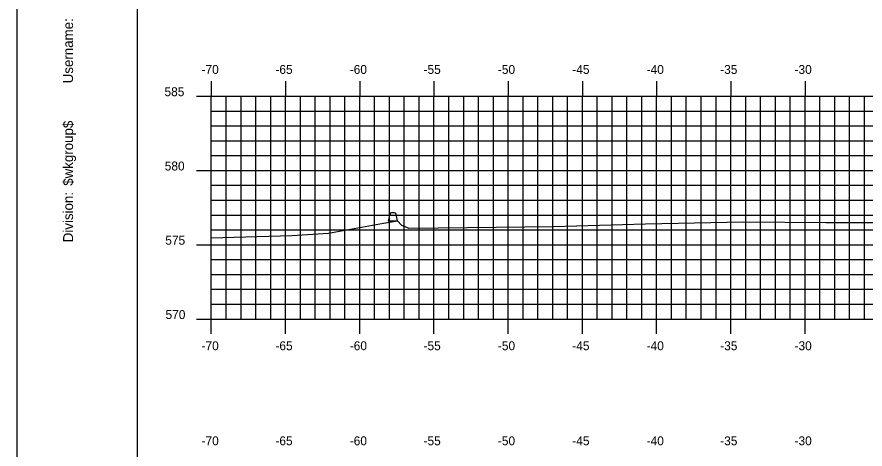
# Model space of a CAD drawing. Extents: x 1048343 to 1048513, y 781387 to 781497.
# Drawn here: x 1048343 to 1048400.2, y 781417.6 to 781446.7 of the extents above; entities that cross this region are included whole.
import ezdxf

# ---------------------------------------------------------------- set-up
doc = ezdxf.new("R2010")
doc.units = 0
for name, color, linetype in [('BORDER', 7, 'Continuous'), ('H_V ANNOTATION', 7, 'Continuous'), ('MAJOR', 7, 'Continuous'), ('MINOR', 7, 'Continuous'), ('PLOT BOUNDARY', 7, 'Continuous'), ('S_Curb_Type_3', 7, 'Continuous'), ('S_Roadway_Centerline', 7, 'Continuous')]:
    doc.layers.add(name, color=color, linetype=linetype)

msp = doc.modelspace()

# ---------------------------------------------------------------- linework, layer by layer
at = {"layer": 'BORDER'}
msp.add_lwpolyline([(1048351.12, 781390.375), (1048511.12, 781390.375), (1048511.12, 781495.375), (1048351.12, 781495.375)], close=True, dxfattribs=at)
at = {"layer": 'MAJOR'}
for p, q in [((1048356.119, 781442.377), (1048356.119, 781441.375)), ((1048361.119, 781442.377), (1048361.119, 781441.375)), ((1048366.119, 781442.377), (1048366.119, 781441.375)), ((1048371.119, 781442.377), (1048371.119, 781441.375)), ((1048376.119, 781442.377), (1048376.119, 781441.375)), ((1048381.119, 781442.377), (1048381.119, 781441.375)), ((1048386.119, 781442.377), (1048386.119, 781441.375)), ((1048391.119, 781442.377), (1048391.119, 781441.375)), ((1048396.119, 781442.377), (1048396.119, 781441.375)), ((1048355.117, 781441.375), (1048356.119, 781441.375)), ((1048356.119, 781441.375), (1048496.119, 781441.375)), ((1048356.119, 781426.375), (1048356.119, 781441.375)), ((1048356.119, 781426.375), (1048356.119, 781441.375)), ((1048356.119, 781441.375), (1048496.119, 781441.375)), ((1048361.119, 781426.375), (1048361.119, 781441.375)), ((1048366.119, 781426.375), (1048366.119, 781441.375)), ((1048371.119, 781426.375), (1048371.119, 781441.375)), ((1048376.119, 781426.375), (1048376.119, 781441.375)), ((1048381.119, 781426.375), (1048381.119, 781441.375)), ((1048386.119, 781426.375), (1048386.119, 781441.375)), ((1048391.119, 781426.375), (1048391.119, 781441.375)), ((1048396.119, 781426.375), (1048396.119, 781441.375)), ((1048355.117, 781436.375), (1048356.119, 781436.375)), ((1048356.119, 781436.375), (1048496.119, 781436.375)), ((1048355.117, 781431.375), (1048356.119, 781431.375)), ((1048356.119, 781431.375), (1048496.119, 781431.375)), ((1048355.117, 781426.375), (1048356.119, 781426.375)), ((1048356.119, 781426.375), (1048496.119, 781426.375)), ((1048356.119, 781426.375), (1048496.119, 781426.375)), ((1048356.119, 781425.373), (1048356.119, 781426.375)), ((1048361.119, 781425.373), (1048361.119, 781426.375)), ((1048366.119, 781425.373), (1048366.119, 781426.375)), ((1048371.119, 781425.373), (1048371.119, 781426.375)), ((1048376.119, 781425.373), (1048376.119, 781426.375)), ((1048381.119, 781425.373), (1048381.119, 781426.375)), ((1048386.119, 781425.373), (1048386.119, 781426.375)), ((1048391.119, 781425.373), (1048391.119, 781426.375)), ((1048396.119, 781425.373), (1048396.119, 781426.375))]:
    msp.add_line(p, q, dxfattribs=at)
at = {"layer": 'MINOR'}
for p, q in [((1048357.119, 781426.375), (1048357.119, 781441.375)), ((1048358.119, 781426.375), (1048358.119, 781441.375)), ((1048359.119, 781426.375), (1048359.119, 781441.375)), ((1048360.119, 781426.375), (1048360.119, 781441.375)), ((1048362.119, 781426.375), (1048362.119, 781441.375)), ((1048363.119, 781426.375), (1048363.119, 781441.375)), ((1048364.119, 781426.375), (1048364.119, 781441.375)), ((1048365.119, 781426.375), (1048365.119, 781441.375)), ((1048367.119, 781426.375), (1048367.119, 781441.375)), ((1048368.119, 781426.375), (1048368.119, 781441.375)), ((1048369.119, 781426.375), (1048369.119, 781441.375)), ((1048370.119, 781426.375), (1048370.119, 781441.375)), ((1048372.119, 781426.375), (1048372.119, 781441.375)), ((1048373.119, 781426.375), (1048373.119, 781441.375)), ((1048374.119, 781426.375), (1048374.119, 781441.375)), ((1048375.119, 781426.375), (1048375.119, 781441.375)), ((1048377.119, 781426.375), (1048377.119, 781441.375)), ((1048378.119, 781426.375), (1048378.119, 781441.375)), ((1048379.119, 781426.375), (1048379.119, 781441.375)), ((1048380.119, 781426.375), (1048380.119, 781441.375)), ((1048382.119, 781426.375), (1048382.119, 781441.375)), ((1048383.119, 781426.375), (1048383.119, 781441.375)), ((1048384.119, 781426.375), (1048384.119, 781441.375)), ((1048385.119, 781426.375), (1048385.119, 781441.375)), ((1048387.119, 781426.375), (1048387.119, 781441.375)), ((1048388.119, 781426.375), (1048388.119, 781441.375)), ((1048389.119, 781426.375), (1048389.119, 781441.375)), ((1048390.119, 781426.375), (1048390.119, 781441.375)), ((1048392.119, 781426.375), (1048392.119, 781441.375)), ((1048393.119, 781426.375), (1048393.119, 781441.375)), ((1048394.119, 781426.375), (1048394.119, 781441.375)), ((1048395.119, 781426.375), (1048395.119, 781441.375)), ((1048397.119, 781426.375), (1048397.119, 781441.375)), ((1048398.119, 781426.375), (1048398.119, 781441.375)), ((1048399.119, 781426.375), (1048399.119, 781441.375)), ((1048400.119, 781426.375), (1048400.119, 781441.375)), ((1048356.119, 781440.375), (1048496.119, 781440.375)), ((1048356.119, 781440.375), (1048357.121, 781440.375)), ((1048356.119, 781439.375), (1048496.119, 781439.375)), ((1048356.119, 781439.375), (1048357.121, 781439.375)), ((1048356.119, 781438.375), (1048496.119, 781438.375)), ((1048356.119, 781438.375), (1048357.121, 781438.375)), ((1048356.119, 781437.375), (1048496.119, 781437.375)), ((1048356.119, 781437.375), (1048357.121, 781437.375)), ((1048356.119, 781435.375), (1048496.119, 781435.375)), ((1048356.119, 781435.375), (1048357.121, 781435.375)), ((1048356.119, 781434.375), (1048496.119, 781434.375)), ((1048356.119, 781434.375), (1048357.121, 781434.375)), ((1048356.119, 781433.375), (1048496.119, 781433.375)), ((1048356.119, 781433.375), (1048357.121, 781433.375)), ((1048356.119, 781432.375), (1048496.119, 781432.375)), ((1048356.119, 781432.375), (1048357.121, 781432.375)), ((1048356.119, 781430.375), (1048496.119, 781430.375)), ((1048356.119, 781430.375), (1048357.121, 781430.375)), ((1048356.119, 781429.375), (1048496.119, 781429.375)), ((1048356.119, 781429.375), (1048357.121, 781429.375)), ((1048356.119, 781428.375), (1048496.119, 781428.375)), ((1048356.119, 781428.375), (1048357.121, 781428.375)), ((1048356.119, 781427.375), (1048496.119, 781427.375)), ((1048356.119, 781427.375), (1048357.121, 781427.375))]:
    msp.add_line(p, q, dxfattribs=at)
at = {"layer": 'PLOT BOUNDARY'}
msp.add_lwpolyline([(1048343.026, 781387.316), (1048513.026, 781387.316), (1048513.026, 781497.316), (1048343.026, 781497.316)], close=True, dxfattribs=at)
at = {"layer": 'S_Curb_Type_3'}
for points in [[(1048368.144, 781433.424), (1048368.042, 781432.979), (1048368.667, 781432.979), (1048368.564, 781433.424)], [(1048368.442, 781433.521), (1048368.266, 781433.521)]]:
    msp.add_lwpolyline(points, dxfattribs=at)
for centre, start, end in [((1048368.266, 781433.396), 90, 167.0054), ((1048368.442, 781433.396), 12.9946, 90)]:
    msp.add_arc(centre, 0.125, start, end, dxfattribs=at)
at = {"layer": 'S_Roadway_Centerline'}
msp.add_lwpolyline([(1048356.119, 781431.834), (1048361.554, 781432), (1048364.015, 781432.152), (1048367.725, 781432.824), (1048368.667, 781432.979), (1048368.932, 781432.685), (1048369.424, 781432.494), (1048369.426, 781432.495), (1048373.374, 781432.545), (1048379.166, 781432.614), (1048385.375, 781432.782), (1048391.977, 781432.919), (1048397.517, 781432.883), (1048403.278, 781432.868)], dxfattribs=at)

# ---------------------------------------------------------------- texts
at = {"layer": 'BORDER'}
for s, p in [('Username:', (1048346.805, 781442.243)), ('$wkgroup$', (1048346.805, 781435.345)), ('Division:', (1048346.805, 781431.542))]:
    msp.add_text(s, height=0.6696, rotation=90, dxfattribs=at).set_placement(p)
at = {"layer": 'H_V ANNOTATION'}
for s, p in [('-70', (1048355.461, 781442.875)), ('-65', (1048360.437, 781442.875)), ('-60', (1048365.445, 781442.875)), ('-55', (1048370.416, 781442.875)), ('-50', (1048375.424, 781442.875)), ('-45', (1048380.437, 781442.875)), ('-40', (1048385.445, 781442.875)), ('-35', (1048390.4, 781442.875)), ('-30', (1048395.408, 781442.875)), ('585', (1048352.965, 781441.375)), ('580', (1048352.981, 781436.375)), ('575', (1048353.019, 781431.375)), ('570', (1048353.035, 781426.375)), ('-70', (1048355.461, 781424.275)), ('-65', (1048360.437, 781424.275)), ('-60', (1048365.445, 781424.275)), ('-55', (1048370.416, 781424.275)), ('-50', (1048375.424, 781424.275)), ('-45', (1048380.437, 781424.275)), ('-40', (1048385.445, 781424.275)), ('-35', (1048390.4, 781424.275)), ('-30', (1048395.408, 781424.275)), ('-70', (1048355.461, 781417.875)), ('-65', (1048360.437, 781417.875)), ('-60', (1048365.445, 781417.875)), ('-55', (1048370.416, 781417.875)), ('-50', (1048375.424, 781417.875)), ('-45', (1048380.437, 781417.875)), ('-40', (1048385.445, 781417.875)), ('-35', (1048390.4, 781417.875)), ('-30', (1048395.408, 781417.875))]:
    msp.add_text(s, height=0.6, dxfattribs=at).set_placement(p)
at = {"layer": 'MAJOR'}
msp.add_text('-', height=0.006, dxfattribs=at).set_placement((1048356.115, 781426.375))
at = {"layer": 'S_Roadway_Centerline'}
for s, p in [('L', (1048391.969, 781432.912)), ('C', (1048391.972, 781432.919))]:
    msp.add_text(s, height=0.0146, dxfattribs=at).set_placement(p)

doc.saveas('drawing.dxf')
